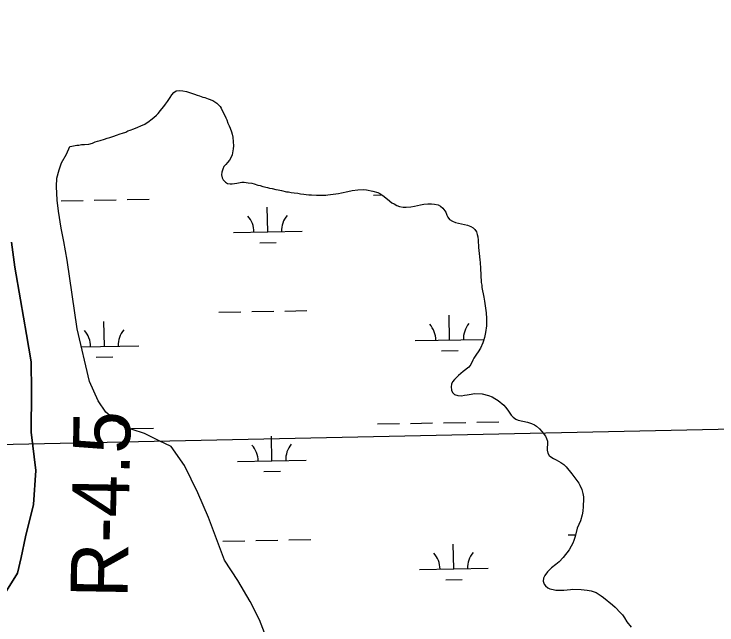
# Model space of a CAD drawing. Extents: x 3957609 to 3995875, y 234277 to 260273.
# Drawn here: x 3968113 to 3969134, y 247420 to 248308 of the extents above; entities that cross this region are included whole.
import ezdxf

# ---------------------------------------------------------------- set-up
doc = ezdxf.new("R2010")
doc.units = 0
for name, color, linetype in [('V-RIVR-RANG-IDEN', 7, 'Continuous'), ('V-TOPO-SHOR', 7, 'Continuous'), ('V-UTIL-LINE', 7, 'Continuous'), ('V-WETL-SWMP', 7, 'Continuous')]:
    doc.layers.add(name, color=color, linetype=linetype)

msp = doc.modelspace()

# ---------------------------------------------------------------- linework, layer by layer
at = {"layer": 'V-TOPO-SHOR'}
for points in [[(3968292.602, 248143.193), (3968297.103, 248145.36), (3968302.506, 248147.842), (3968308.791, 248152.145), (3968311.484, 248153.988), (3968315.67, 248157.359), (3968319.85, 248161.033), (3968321.935, 248163.472), (3968325.509, 248167.439), (3968327.592, 248169.88), (3968330.563, 248173.538), (3968332.943, 248176.585), (3968335.61, 248180.542), (3968339.46, 248186.627), (3968342.128, 248190.584), (3968345.104, 248193.94), (3968348.399, 248196.093), (3968353.829, 248196.461), (3968357.755, 248196.207), (3968363.202, 248195.067), (3968368.957, 248193.326), (3968375.017, 248191.589), (3968378.656, 248190.125), (3968381.991, 248188.957), (3968387.143, 248187.21), (3968390.172, 248186.34), (3968395.024, 248184.589), (3968401.395, 248181.951), (3968407.177, 248178.097), (3968412.061, 248173.63), (3968413.603, 248170.933), (3968416.08, 248165.831), (3968417.935, 248162.231), (3968420.415, 248156.828), (3968421.961, 248153.828), (3968423.53, 248149.019), (3968425.087, 248145.114), (3968426.637, 248141.812), (3968428.515, 248136.402), (3968429.459, 248133.092), (3968430.418, 248128.879), (3968431.102, 248122.248), (3968431.775, 248116.52), (3968431.227, 248111.985), (3968430.659, 248108.96), (3968429.826, 248103.216), (3968427.763, 248098.964), (3968425.693, 248095.62), (3968422.717, 248091.96), (3968420.337, 248089.216), (3968417.659, 248086.164), (3968416.196, 248082.222), (3968414.437, 248077.974), (3968414.183, 248074.046), (3968415.142, 248069.833), (3968416.688, 248066.833), (3968420.051, 248063.253), (3968422.785, 248061.777), (3968426.717, 248061.222), (3968429.738, 248060.955), (3968436.367, 248061.942), (3968443.59, 248063.54), (3968447.215, 248063.284), (3968452.958, 248062.749), (3968458.098, 248061.908)], [(3968193.634, 248115.422), (3968196.649, 248115.76), (3968203.876, 248117.054), (3968206.891, 248117.394), (3968210.505, 248118.041), (3968215.034, 248118.097), (3968221.364, 248118.779), (3968226.476, 248120.349), (3968230.379, 248121.908), (3968233.992, 248122.856), (3968237.596, 248124.107), (3968243.912, 248125.996), (3968247.822, 248127.251), (3968251.73, 248128.507), (3968257.441, 248130.387), (3968261.347, 248131.943), (3968267.059, 248133.825), (3968270.065, 248134.767), (3968275.177, 248136.338), (3968277.876, 248137.88), (3968281.483, 248139.134), (3968286.591, 248141.006), (3968292.602, 248143.193)], [(3968481.628, 247396.003), (3968469.19, 247427.583), (3968456.009, 247454.334), (3968437.966, 247484.642), (3968418.726, 247514.129), (3968405.442, 247549.316), (3968395.475, 247576.108), (3968379.771, 247612.067), (3968360.405, 247651.996), (3968340.789, 247679.474), (3968323.416, 247687.697), (3968302.397, 247698.285), (3968284.252, 247704.087), (3968266.885, 247711.911), (3968246.186, 247729.331), (3968235.141, 247745.666), (3968222.341, 247774.029), (3968204.535, 247850.532), (3968190.064, 247949.97), (3968184.912, 247977.223), (3968181.061, 247996.456), (3968177.141, 248021.312), (3968175.339, 248037.356), (3968174.297, 248057.027), (3968174.952, 248069.086), (3968178.018, 248081.173), (3968181.504, 248091.659), (3968188.983, 248104.203), (3968193.634, 248115.422)], [(3968458.098, 248061.908), (3968461.731, 248061.045), (3968466.884, 248059.296), (3968470.212, 248058.733), (3968474.456, 248057.277), (3968480.815, 248055.545), (3968484.147, 248054.678), (3968487.776, 248054.119), (3968493.222, 248052.978), (3968496.55, 248052.415), (3968501.389, 248051.569), (3968508.657, 248049.546), (3968511.68, 248049.282), (3968515.614, 248048.424), (3968519.544, 248047.867), (3968525.283, 248047.635), (3968529.221, 248046.476), (3968533.756, 248045.927), (3968537.381, 248045.671), (3968541.01, 248045.11), (3968544.938, 248044.858)], [(3968544.938, 248044.858), (3968552.394, 248044.594), (3968565.766, 248044.711), (3968568.883, 248045.286), (3968583.987, 248047.088), (3968588.509, 248048.11), (3968598.016, 248049.839), (3968603.943, 248051.152), (3968612.511, 248052.581), (3968620.13, 248052.626), (3968624.787, 248052.247), (3968634.087, 248050.402), (3968641.368, 248048.587), (3968644.143, 248046.992), (3968648.454, 248044.131), (3968655.368, 248038.591), (3968661.825, 248033.678), (3968664.905, 248031.767), (3968669.225, 248029.373), (3968672.782, 248028.234), (3968678.209, 248027.378), (3968682.408, 248027.317), (3968689.41, 248027.837), (3968694.861, 248028.689), (3968703.281, 248030.434), (3968708.268, 248031.294), (3968714.184, 248031.984), (3968719.628, 248032.062), (3968723.974, 248031.687), (3968729.088, 248030.524), (3968732.635, 248028.607), (3968735.856, 248025.763), (3968740.278, 248019.793), (3968741.775, 248015.729), (3968743.284, 248012.754), (3968745.724, 248009.454), (3968749.881, 248006.595), (3968754.36, 248004.664), (3968771.563, 248001.152), (3968776.505, 247998.903), (3968779.743, 247997.146), (3968782.51, 247994.93), (3968784.787, 247991.321), (3968785.973, 247987.262), (3968786.702, 247983.987), (3968787.255, 247979.16), (3968787.875, 247968.427), (3968788.838, 247959.862), (3968789.481, 247950.525), (3968789.895, 247946.945), (3968790.546, 247938.231), (3968790.876, 247928.745), (3968791.65, 247917.851), (3968792.367, 247913.798), (3968792.782, 247910.218), (3968795.535, 247896.343), (3968796.383, 247890.58), (3968798.623, 247873.604), (3968799.123, 247865.203), (3968799.127, 247854.787), (3968798.05, 247844.854), (3968796.551, 247837.881), (3968795.08, 247833.085), (3968793.946, 247829.837), (3968790.728, 247822.423)], [(3968101.664, 247469.657), (3968117.817, 247495.562), (3968123.164, 247518.121), (3968129.222, 247548.32), (3968140.701, 247595.056), (3968144.517, 247644.509), (3968137.408, 247700.255), (3968137.885, 247759.711), (3968137.365, 247802.283), (3968130.85, 247842.37), (3968121.802, 247892.47), (3968113.588, 247940.168), (3968108.728, 247976.26)], [(3968790.728, 247822.423), (3968787.075, 247816.729), (3968784.697, 247813.502), (3968780.888, 247807.812), (3968779.29, 247804.728), (3968776.716, 247798.553), (3968773.707, 247794.56), (3968765.229, 247788.162), (3968758.468, 247782.513), (3968752.636, 247776.541), (3968749.947, 247773.162), (3968748.501, 247769.769), (3968748.136, 247766.201), (3968748.531, 247761.226), (3968749.881, 247757.946), (3968752.941, 247754.796), (3968757.733, 247753.327), (3968762.857, 247753.254), (3968767.525, 247753.807), (3968771.104, 247754.376), (3968774.377, 247755.105), (3968782.469, 247756.229), (3968793.024, 247755.92), (3968802.461, 247753.454), (3968807.557, 247751.361), (3968811.565, 247749.285), (3968816.486, 247746.106), (3968824.465, 247739.469), (3968827.066, 247736.634), (3968830.419, 247732.237), (3968835.123, 247724.717), (3968838.191, 247722.032), (3968841.877, 247719.337), (3968845.426, 247717.733), (3968858.736, 247714.589), (3968864.77, 247712.949), (3968869.089, 247710.866), (3968872.163, 247708.804), (3968876.458, 247705.015), (3968879.976, 247701.39), (3968885.002, 247694.484), (3968886.661, 247691.199), (3968887.842, 247686.989), (3968887.928, 247682.174), (3968887.398, 247677.834), (3968887.5, 247674.105), (3968888.68, 247669.894), (3968890.495, 247666.451), (3968892.792, 247664.243), (3968896.641, 247661.858), (3968900.81, 247660.244), (3968907.585, 247656.264), (3968911.732, 247653.096), (3968914.948, 247649.944), (3968923.187, 247639.731), (3968933.39, 247625.915), (3968935.057, 247623.097), (3968938.07, 247616.687), (3968939.387, 247611.075), (3968940.095, 247606.406), (3968940.357, 247603.141), (3968939.888, 247592.121), (3968939.171, 247585.61), (3968938.311, 247579.876), (3968935.862, 247571.526), (3968930.887, 247560.572), (3968928.229, 247548.652), (3968927.412, 247545.713), (3968926.279, 247542.625), (3968924.672, 247538.92), (3968922.591, 247534.603), (3968919.253, 247529.37), (3968910.549, 247518.16), (3968905.023, 247512.028), (3968900.149, 247507.752), (3968893.71, 247502.875), (3968891.347, 247500.58), (3968888.191, 247497.053), (3968884.234, 247491.986), (3968882.315, 247488.132), (3968881.629, 247483.638), (3968883.122, 247479.577), (3968885.258, 247476.907), (3968888.479, 247474.22), (3968891.408, 247472.78), (3968896.209, 247471.779), (3968900.231, 247470.634), (3968903.334, 247470.433), (3968911.876, 247470.464), (3968921.211, 247471.725), (3968924.786, 247471.985), (3968936.898, 247471.809), (3968945.733, 247470.748), (3968951.619, 247469.577), (3968955.795, 247468.428), (3968958.572, 247467.146), (3968965.804, 247462.538), (3968969.187, 247460.158), (3968982.542, 247449.56), (3968986.374, 247445.933), (3968994.175, 247437.743)], [(3968994.175, 247437.743), (3968996.769, 247434.599), (3968999.968, 247430.36), (3969003.298, 247424.41), (3969009.555, 247416.866)]]:
    msp.add_lwpolyline(points, dxfattribs=at)
at = {"layer": 'V-UTIL-LINE'}
msp.add_lwpolyline([(3961767.682, 245361.868), (3961943.705, 245468.964), (3965208.639, 247597.169), (3966396.749, 247622.307), (3967484.854, 247669.667), (3969697.646, 247716.332), (3970569.601, 248052.102), (3971717.759, 248552.062), (3975420.027, 250066.441), (3979384.42, 251663.69), (3984441.626, 253334.756), (3993476.194, 256555.397)], dxfattribs=at)
at = {"layer": 'V-WETL-SWMP'}
for p, q in [((3968635.036, 248044.739), (3968647.205, 248044.96)), ((3968181.203, 248036.487), (3968213.198, 248037.068)), ((3968229.195, 248037.359), (3968261.19, 248037.941)), ((3968277.187, 248038.232), (3968309.182, 248038.814)), ((3968481.392, 247991.195), (3968480.738, 248027.189)), ((3968431.401, 247990.286), (3968531.384, 247992.104)), ((3968469.675, 247975.548), (3968493.671, 247975.984)), ((3968506.079, 247876.192), (3968538.074, 247876.774)), ((3968410.095, 247874.447), (3968442.09, 247875.029)), ((3968458.087, 247875.32), (3968490.082, 247875.902)), ((3968745.728, 247834.112), (3968745.073, 247870.106)), ((3968243.903, 247824.988), (3968243.248, 247860.982)), ((3968210.622, 247824.382), (3968293.895, 247825.897)), ((3968695.736, 247833.203), (3968795.674, 247835.021)), ((3968734.01, 247818.466), (3968758.006, 247818.902)), ((3968232.185, 247809.341), (3968256.181, 247809.777)), ((3968689.076, 247712.991), (3968721.071, 247713.573)), ((3968737.069, 247713.864), (3968769.063, 247714.446)), ((3968785.061, 247714.737), (3968817.055, 247715.318)), ((3968283.236, 247705.612), (3968315.23, 247706.194)), ((3968641.084, 247712.119), (3968673.079, 247712.701)), ((3968487.44, 247658.575), (3968486.786, 247694.569)), ((3968437.449, 247657.666), (3968537.432, 247659.484)), ((3968475.723, 247642.928), (3968499.719, 247643.364)), ((3968917.968, 247550.952), (3968928.787, 247551.149)), ((3968416.143, 247541.827), (3968448.138, 247542.409)), ((3968464.135, 247542.7), (3968496.13, 247543.282)), ((3968512.127, 247543.572), (3968544.122, 247544.154)), ((3968751.776, 247501.492), (3968751.121, 247537.486)), ((3968701.784, 247500.583), (3968801.768, 247502.401)), ((3968740.058, 247485.846), (3968764.054, 247486.282))]:
    msp.add_line(p, q, dxfattribs=at)
for points in [[(3968292.601, 248143.193), (3968297.102, 248145.36), (3968302.505, 248147.841), (3968308.791, 248152.144), (3968311.485, 248153.988), (3968315.67, 248157.359), (3968319.851, 248161.032), (3968321.934, 248163.473), (3968325.508, 248167.44), (3968327.591, 248169.881), (3968330.564, 248173.539), (3968332.942, 248176.586), (3968335.61, 248180.543), (3968339.46, 248186.627), (3968342.128, 248190.584), (3968345.105, 248193.94), (3968348.399, 248196.093), (3968353.828, 248196.462), (3968357.755, 248196.208), (3968363.202, 248195.067), (3968368.958, 248193.326), (3968375.017, 248191.589), (3968378.657, 248190.124), (3968381.991, 248188.958), (3968387.144, 248187.21), (3968390.173, 248186.341), (3968395.024, 248184.589), (3968401.395, 248181.951), (3968407.177, 248178.097), (3968412.061, 248173.63), (3968413.603, 248170.932), (3968416.08, 248165.831), (3968417.935, 248162.231), (3968420.416, 248156.828), (3968421.962, 248153.829), (3968423.53, 248149.019), (3968425.087, 248145.114), (3968426.636, 248141.812), (3968428.514, 248136.402), (3968429.46, 248133.093), (3968430.417, 248128.879), (3968431.101, 248122.247), (3968431.775, 248116.52), (3968431.227, 248111.986), (3968430.66, 248108.961), (3968429.825, 248103.215), (3968427.764, 248098.964), (3968425.692, 248095.619), (3968422.718, 248091.96), (3968420.337, 248089.215), (3968417.658, 248086.164), (3968416.197, 248082.222), (3968414.437, 248077.974), (3968414.184, 248074.047), (3968415.141, 248069.833), (3968416.687, 248066.834), (3968420.051, 248063.253), (3968422.785, 248061.777), (3968426.716, 248061.221), (3968429.738, 248060.956), (3968436.366, 248061.943), (3968443.591, 248063.54), (3968447.216, 248063.283), (3968452.958, 248062.749), (3968458.099, 248061.907), (3968461.732, 248061.046), (3968466.885, 248059.297), (3968470.212, 248058.734), (3968474.455, 248057.277), (3968480.815, 248055.544), (3968484.146, 248054.679), (3968487.775, 248054.12), (3968493.222, 248052.979), (3968496.549, 248052.416), (3968501.389, 248051.569), (3968508.658, 248049.545), (3968511.68, 248049.281), (3968515.614, 248048.423), (3968519.545, 248047.867), (3968525.283, 248047.636), (3968529.221, 248046.476), (3968533.755, 248045.928), (3968537.38, 248045.671), (3968541.009, 248045.111), (3968544.937, 248044.858), (3968552.395, 248044.594), (3968565.765, 248044.711), (3968568.882, 248045.287), (3968583.986, 248047.089), (3968588.509, 248048.111), (3968598.016, 248049.839), (3968603.942, 248051.152), (3968612.512, 248052.581), (3968620.13, 248052.626), (3968624.788, 248052.248), (3968634.088, 248050.403), (3968641.367, 248048.587), (3968644.142, 248046.992), (3968648.453, 248044.132), (3968655.367, 248038.591), (3968661.825, 248033.678)], [(3968481.627, 247396.002), (3968469.191, 247427.582), (3968456.01, 247454.334), (3968437.966, 247484.641), (3968418.726, 247514.13), (3968405.442, 247549.316), (3968395.475, 247576.107), (3968379.771, 247612.066), (3968360.404, 247651.997), (3968340.788, 247679.474), (3968323.415, 247687.697), (3968302.398, 247698.285), (3968284.252, 247704.088), (3968266.884, 247711.91), (3968246.185, 247729.331), (3968235.14, 247745.665), (3968222.341, 247774.028), (3968204.536, 247850.531), (3968190.065, 247949.971), (3968184.911, 247977.222), (3968181.061, 247996.456), (3968177.142, 248021.312), (3968175.339, 248037.357), (3968174.296, 248057.027), (3968174.952, 248069.085), (3968178.017, 248081.173), (3968181.504, 248091.66), (3968188.983, 248104.203), (3968193.634, 248115.421), (3968196.649, 248115.759), (3968203.877, 248117.055), (3968206.891, 248117.394), (3968210.506, 248118.042), (3968215.033, 248118.097), (3968221.363, 248118.778), (3968226.475, 248120.35), (3968230.38, 248121.907), (3968233.991, 248122.856), (3968237.597, 248124.108), (3968243.913, 248125.996), (3968247.822, 248127.251), (3968251.73, 248128.506), (3968257.442, 248130.387), (3968261.347, 248131.944), (3968267.059, 248133.825), (3968270.066, 248134.767), (3968275.178, 248136.339), (3968277.876, 248137.881), (3968281.483, 248139.133), (3968286.591, 248141.006), (3968292.601, 248143.193)], [(3968661.825, 248033.678), (3968664.906, 248031.768), (3968669.224, 248029.374), (3968672.782, 248028.234), (3968678.21, 248027.378), (3968682.407, 248027.317), (3968689.409, 248027.837), (3968694.862, 248028.69), (3968703.281, 248030.434), (3968708.268, 248031.294), (3968714.185, 248031.985), (3968719.627, 248032.062), (3968723.974, 248031.687), (3968729.087, 248030.525), (3968732.634, 248028.608), (3968735.857, 248025.763), (3968740.278, 248019.792), (3968741.774, 248015.729), (3968743.285, 248012.754), (3968745.724, 248009.454), (3968749.88, 248006.595), (3968754.36, 248004.665), (3968771.563, 248001.151), (3968776.504, 247998.903), (3968779.743, 247997.146), (3968782.509, 247994.93), (3968784.788, 247991.321), (3968785.973, 247987.262), (3968786.703, 247983.987), (3968787.254, 247979.161), (3968787.876, 247968.426), (3968788.839, 247959.862), (3968789.481, 247950.526), (3968789.895, 247946.945), (3968790.546, 247938.231), (3968790.875, 247928.744), (3968791.649, 247917.851), (3968792.367, 247913.799), (3968792.782, 247910.218), (3968795.534, 247896.344), (3968796.383, 247890.58), (3968798.623, 247873.604), (3968799.123, 247865.203), (3968799.127, 247854.788), (3968798.05, 247844.855), (3968796.55, 247837.882), (3968795.081, 247833.084), (3968793.946, 247829.836), (3968790.729, 247822.422), (3968787.074, 247816.729), (3968784.698, 247813.502), (3968780.888, 247807.812), (3968779.291, 247804.729), (3968776.716, 247798.554), (3968773.707, 247794.56), (3968765.228, 247788.161), (3968758.468, 247782.513), (3968752.636, 247776.541), (3968749.947, 247773.163), (3968748.5, 247769.768), (3968748.137, 247766.201), (3968748.531, 247761.226), (3968749.881, 247757.945), (3968752.941, 247754.795), (3968757.734, 247753.327), (3968762.858, 247753.253), (3968767.525, 247753.806), (3968771.105, 247754.376), (3968774.377, 247755.105), (3968782.469, 247756.229), (3968793.024, 247755.921), (3968802.462, 247753.454), (3968807.556, 247751.361), (3968811.564, 247749.284), (3968816.487, 247746.107), (3968824.466, 247739.468), (3968827.065, 247736.635), (3968830.418, 247732.238), (3968835.123, 247724.716), (3968838.19, 247722.031), (3968841.878, 247719.337), (3968845.427, 247717.733), (3968858.737, 247714.589), (3968864.769, 247712.948), (3968869.088, 247710.867), (3968872.164, 247708.803), (3968876.457, 247705.014), (3968879.976, 247701.391), (3968885.001, 247694.484), (3968886.661, 247691.199), (3968887.843, 247686.989), (3968887.928, 247682.173), (3968887.399, 247677.833), (3968887.5, 247674.104), (3968888.681, 247669.894), (3968890.495, 247666.451), (3968892.792, 247664.243), (3968896.64, 247661.858), (3968900.81, 247660.244), (3968907.585, 247656.264), (3968911.732, 247653.097)], [(3968108.728, 247976.261), (3968113.588, 247940.169), (3968121.803, 247892.47), (3968130.85, 247842.37), (3968137.366, 247802.282)], [(3968137.366, 247802.282), (3968137.886, 247759.71), (3968137.408, 247700.256), (3968144.516, 247644.509), (3968140.702, 247595.055), (3968129.223, 247548.32), (3968123.165, 247518.12), (3968117.817, 247495.561), (3968101.665, 247469.656)], [(3968911.732, 247653.097), (3968914.948, 247649.945), (3968923.186, 247639.731), (3968933.39, 247625.916), (3968935.057, 247623.097), (3968938.07, 247616.686), (3968939.386, 247611.076), (3968940.095, 247606.406), (3968940.358, 247603.141), (3968939.888, 247592.122), (3968939.172, 247585.61), (3968938.312, 247579.876), (3968935.861, 247571.526), (3968930.888, 247560.572), (3968928.23, 247548.652), (3968927.411, 247545.714), (3968926.279, 247542.624), (3968924.672, 247538.92), (3968922.59, 247534.602), (3968919.253, 247529.37), (3968910.549, 247518.16), (3968905.024, 247512.028), (3968900.148, 247507.751), (3968893.71, 247502.875), (3968891.347, 247500.58), (3968888.19, 247497.053), (3968884.234, 247491.986), (3968882.314, 247488.132), (3968881.628, 247483.638), (3968883.122, 247479.578), (3968885.257, 247476.907), (3968888.48, 247474.22), (3968891.409, 247472.78), (3968896.209, 247471.779), (3968900.23, 247470.633), (3968903.333, 247470.433), (3968911.875, 247470.464), (3968921.211, 247471.726), (3968924.787, 247471.985), (3968936.898, 247471.809), (3968945.734, 247470.749), (3968951.619, 247469.576), (3968955.795, 247468.428), (3968958.572, 247467.146), (3968965.804, 247462.537), (3968969.186, 247460.158), (3968982.543, 247449.559), (3968986.373, 247445.932), (3968994.174, 247437.743), (3968996.769, 247434.599), (3968999.968, 247430.36), (3969003.298, 247424.41), (3969009.556, 247416.865)]]:
    msp.add_lwpolyline(points, dxfattribs=at)
for centre, start, end in [((3968426.15, 247990.665), 0.269879, 41.813537), ((3968536.618, 247992.674), 140.269876, 181.813534), ((3968690.485, 247833.583), 0.269879, 41.813537), ((3968800.953, 247835.591), 140.269876, 181.813534), ((3968188.66, 247824.458), 0.269879, 41.813537), ((3968299.128, 247826.467), 140.269876, 181.813534), ((3968542.666, 247660.054), 140.269876, 181.813534), ((3968432.198, 247658.045), 0.269879, 41.813537), ((3968696.533, 247500.963), 0.269879, 41.813537), ((3968807.001, 247502.971), 140.269876, 181.813534)]:
    msp.add_arc(centre, 35.246, start, end, dxfattribs=at)

# ---------------------------------------------------------------- texts
at = {"layer": 'V-RIVR-RANG-IDEN'}
msp.add_text('R-4.5', height=83, rotation=89.026688, dxfattribs=at).set_placement((3968277.575, 247458.823))

doc.saveas('drawing.dxf')
